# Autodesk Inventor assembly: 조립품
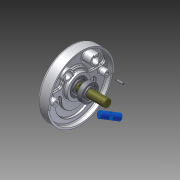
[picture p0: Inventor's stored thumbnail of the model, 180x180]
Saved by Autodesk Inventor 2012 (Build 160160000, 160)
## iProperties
Created: 2015-04
Part Number: 조립품
Document SubType Name: Assembly
Designer: Owner
Author: Owner
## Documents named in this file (7)
- C:\Documents and Settings\Owner\바탕 화면\450405V1008\조립품.iam
- C:\Documents and Settings\Owner\바탕 화면\450405V1008\문제보기2.ipt
- C:\Documents and Settings\Owner\바탕 화면\450405V1008\덮개.ipt
- C:\Documents and Settings\Owner\바탕 화면\450405V1008\베어링62_22.ipt
- C:\Documents and Settings\Owner\바탕 화면\450405V1008\축.ipt
- C:\Documents and Settings\Owner\바탕 화면\450405V1008\평행핀.ipt
- C:\Documents and Settings\Owner\바탕 화면\450405V1008\슬라이더.ipt
